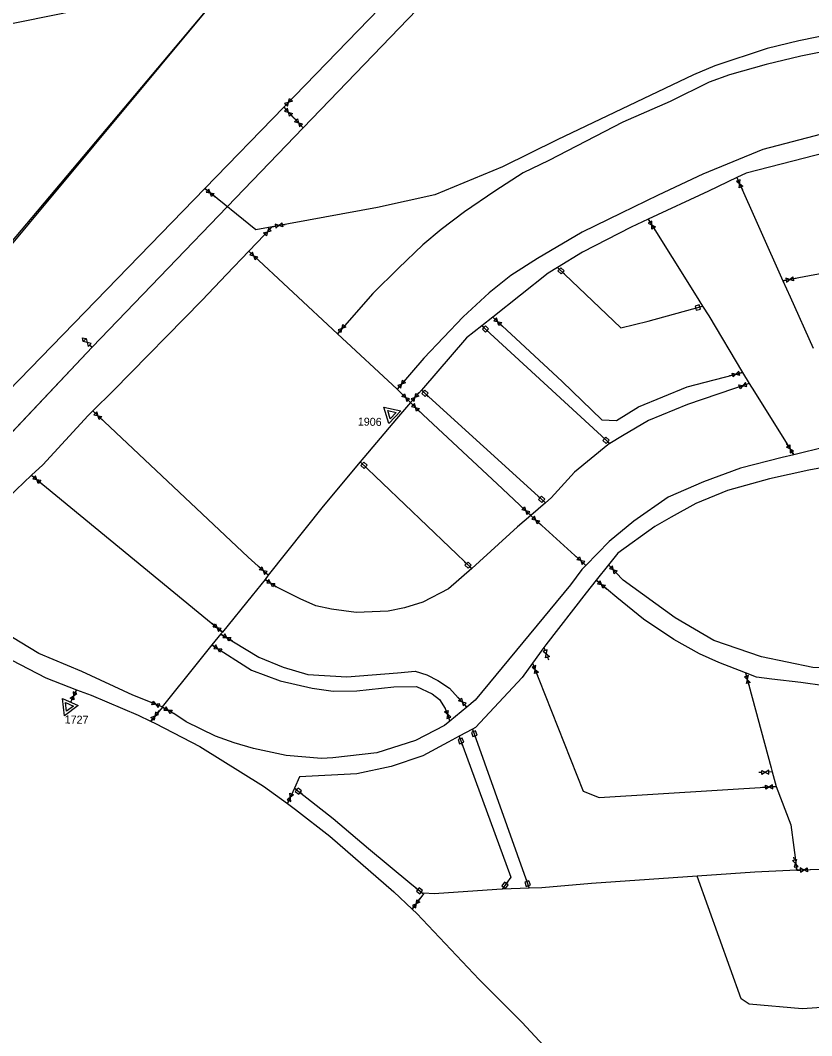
# Model space of a CAD drawing. Extents: x 349903 to 372392, y 368574 to 383062.
# Drawn here: x 363630 to 364124, y 372366 to 373000 of the extents above; entities that cross this region are included whole.
import ezdxf

# ---------------------------------------------------------------- set-up
doc = ezdxf.new("R2010")
doc.units = 0
for name, color, linetype in [('Niveau 1', 7, 'Continuous'), ('Niveau 10', 7, 'Continuous'), ('Niveau 2', 7, 'Continuous'), ('Niveau 3', 7, 'Continuous'), ('Niveau 8', 7, 'Continuous')]:
    doc.layers.add(name, color=color, linetype=linetype)

msp = doc.modelspace()

# ---------------------------------------------------------------- linework, layer by layer
at = {"layer": 'Niveau 1'}
for p, q in [((363794.398, 372946.095), (363795.868, 372947.601)), ((363798.925, 372950.737), (363800.253, 372952.098)), ((363794.398, 372946.095), (363795.842, 372944.564)), ((363798.849, 372941.38), (363800.154, 372939.997)), ((363802.105, 372937.95), (363800.804, 372939.337)), ((363806.543, 372933.223), (363805.103, 372934.757)), ((364077.454, 372902.271), (364078.305, 372900.346)), ((363745.073, 372895.381), (363746.713, 372894.062)), ((363750.126, 372891.317), (363751.607, 372890.126)), ((364080.076, 372896.341), (364080.845, 372894.602)), ((363787.143, 372871.393), (363785.689, 372869.871)), ((363787.143, 372871.393), (363789.212, 372871.781)), ((363793.516, 372872.589), (363795.385, 372872.939)), ((364022.042, 372876.157), (364023.152, 372874.369)), ((363782.665, 372866.704), (363781.351, 372865.329)), ((364025.462, 372870.649), (364026.466, 372869.033)), ((363772.563, 372856.214), (363774.103, 372854.78)), ((363777.309, 372851.797), (363778.701, 372850.501)), ((364106.192, 372837.789), (364108.262, 372838.169)), ((364112.569, 372838.96), (364114.44, 372839.303)), ((363924.923, 372815.068), (363926.464, 372813.635)), ((363832.288, 372809.52), (363833.553, 372810.939)), ((363929.672, 372810.654), (363931.065, 372809.359)), ((363827.973, 372804.68), (363829.374, 372806.25)), ((363869.525, 372774.885), (363870.774, 372776.319)), ((364074.75, 372778.888), (364072.91, 372778.408)), ((364081.024, 372780.525), (364078.988, 372779.994)), ((363865.266, 372769.996), (363866.648, 372771.583)), ((364079.052, 372771.508), (364077.255, 372770.887)), ((364085.18, 372773.628), (364083.191, 372772.94)), ((363869.031, 372766.284), (363867.694, 372767.636)), ((363877.832, 372766.575), (363879.076, 372768.013)), ((363873.589, 372761.673), (363872.11, 372763.17)), ((363873.589, 372761.673), (363874.966, 372763.265)), ((363873.589, 372761.673), (363875.093, 372760.201)), ((363878.223, 372757.138), (363879.582, 372755.809)), ((363675.157, 372756.434), (363676.696, 372754.999)), ((363679.899, 372752.012), (363681.29, 372750.716)), ((364109.487, 372734.589), (364108.481, 372736.202)), ((364112.916, 372729.086), (364111.803, 372730.872)), ((363636.933, 372716.325), (363638.552, 372714.98)), ((363641.921, 372712.183), (363643.384, 372710.968)), ((363943.961, 372695.625), (363942.578, 372696.93)), ((363948.679, 372691.177), (363947.148, 372692.621)), ((363948.679, 372691.177), (363950.236, 372689.761)), ((363953.478, 372686.816), (363954.885, 372685.537)), ((363978.356, 372664.364), (363976.95, 372665.644)), ((363779.943, 372658.177), (363778.54, 372659.46)), ((363983.15, 372659.999), (363981.594, 372661.416)), ((363997.27, 372660.376), (363998.717, 372658.848)), ((364001.73, 372655.669), (364003.037, 372654.289)), ((363782.705, 372651.253), (363784.467, 372650.102)), ((363784.727, 372653.801), (363783.175, 372655.222)), ((363989.588, 372650.835), (363991.201, 372649.483)), ((363788.134, 372647.709), (363789.727, 372646.669)), ((363994.558, 372646.67), (363996.015, 372645.449)), ((363751.072, 372622.466), (363749.6, 372623.668)), ((363756.094, 372618.364), (363754.464, 372619.695)), ((363755.124, 372617.175), (363756.928, 372616.092)), ((363760.684, 372613.84), (363762.315, 372612.862)), ((363751.367, 372609.249), (363749.591, 372610.394)), ((363755.041, 372606.882), (363756.639, 372605.852)), ((363956.92, 372608.822), (363957.642, 372606.845)), ((363949.83, 372598.957), (363950.62, 372597.007)), ((363959.145, 372602.732), (363959.797, 372600.946)), ((363952.265, 372592.948), (363952.98, 372591.186)), ((364082.846, 372592.881), (364083.394, 372590.849)), ((364084.536, 372586.621), (364085.032, 372584.786)), ((363664.038, 372580.482), (363664.953, 372582.387)), ((363662.146, 372576.542), (363661.323, 372574.828)), ((363712.385, 372574.096), (363710.616, 372574.792)), ((363904.494, 372576.333), (363903.228, 372577.751)), ((363716.52, 372569.296), (363715.196, 372567.66)), ((363718.418, 372571.719), (363716.46, 372572.491)), ((363718.418, 372571.719), (363720.233, 372570.653)), ((363724.01, 372568.437), (363725.65, 372567.475)), ((363895.98, 372568.911), (363895.322, 372570.695)), ((363908.81, 372571.494), (363907.409, 372573.065)), ((363712.442, 372564.255), (363711.247, 372562.776)), ((363898.224, 372562.828), (363897.496, 372564.802)), ((364092.993, 372530.698), (364091.095, 372530.58)), ((364099.464, 372531.102), (364097.364, 372530.971)), ((363799.434, 372517.172), (363800.201, 372518.912)), ((364095.38, 372521.522), (364093.482, 372521.409)), ((364101.852, 372521.908), (364099.751, 372521.783)), ((363796.817, 372511.24), (363797.666, 372513.165)), ((364113.402, 372476.006), (364112.948, 372477.852)), ((364114.953, 372469.71), (364114.45, 372471.753)), ((364114.953, 372469.71), (364117.055, 372469.792)), ((364121.432, 372469.965), (364123.332, 372470.039)), ((363874.664, 372445.254), (363875.895, 372446.961)), ((363878.456, 372450.514), (363879.568, 372452.056))]:
    msp.add_line(p, q, dxfattribs=at)
for points in [[(363798.015, 372951.619), (363799.827, 372949.863), (363794.969, 372948.497), (363796.77, 372946.728)], [(363799.768, 372942.253), (363797.939, 372940.515), (363796.774, 372945.425), (363794.933, 372943.699)], [(363801.183, 372937.08), (363803.018, 372938.812), (363804.169, 372933.899), (363806.014, 372935.621)], [(364081.234, 372896.857), (364078.929, 372895.83), (364079.47, 372900.846), (364077.159, 372899.833)], [(363750.917, 372892.308), (363749.342, 372890.337), (363747.518, 372895.042), (363745.931, 372893.08)], [(363793.278, 372873.834), (363793.751, 372871.356), (363788.991, 372873.03), (363789.448, 372870.548)], [(364026.538, 372871.321), (364024.398, 372869.983), (364024.237, 372875.026), (364022.089, 372873.702)], [(363783.584, 372865.831), (363781.754, 372867.568), (363786.597, 372868.985), (363784.778, 372870.734)], [(363778.17, 372852.728), (363776.457, 372850.875), (363774.978, 372855.699), (363773.253, 372853.857)], [(364112.337, 372840.206), (364112.8, 372837.725), (364108.047, 372839.419), (364108.494, 372836.935)], [(363930.533, 372811.585), (363928.821, 372809.732), (363927.338, 372814.555), (363925.614, 372812.712)], [(363831.339, 372810.36), (363833.228, 372808.687), (363828.436, 372807.105), (363830.314, 372805.42)], [(364075.074, 372777.662), (364074.429, 372780.102), (364079.295, 372778.763), (364078.665, 372781.207)], [(363868.566, 372775.715), (363870.474, 372774.064), (363865.701, 372772.426), (363867.599, 372770.763)], [(364079.471, 372770.311), (364078.638, 372772.693), (364083.593, 372771.737), (364082.775, 372774.125)], [(363868.132, 372765.39), (363869.921, 372767.169), (363871.198, 372762.288), (363872.998, 372764.056)], [(363876.871, 372767.402), (363878.783, 372765.757), (363874.016, 372764.105), (363875.919, 372762.447)], [(363879.107, 372758.047), (363877.348, 372756.239), (363875.99, 372761.098), (363874.219, 372759.3)], [(363680.761, 372752.943), (363679.046, 372751.092), (363677.571, 372755.917), (363675.844, 372754.077)], [(364108.412, 372733.915), (364110.55, 372735.256), (364110.719, 372730.213), (364112.865, 372731.541)], [(363642.728, 372713.161), (363641.123, 372711.215), (363639.373, 372715.947), (363637.754, 372714.011)], [(363943.094, 372694.7), (363944.82, 372696.541), (363946.268, 372691.708), (363948.005, 372693.538)], [(363954.328, 372687.757), (363952.636, 372685.885), (363951.099, 372690.69), (363949.396, 372688.829)], [(363977.505, 372663.424), (363979.198, 372665.295), (363980.73, 372660.487), (363982.435, 372662.348)], [(363779.09, 372657.239), (363780.787, 372659.106), (363782.308, 372654.295), (363784.017, 372656.152)], [(364002.647, 372656.544), (364000.821, 372654.803), (363999.647, 372659.711), (363997.81, 372657.981)], [(363788.824, 372648.773), (363787.452, 372646.655), (363785.172, 372651.157), (363783.786, 372649.048)], [(363995.369, 372647.645), (363993.754, 372645.706), (363992.026, 372650.446), (363990.399, 372648.517)], [(363750.273, 372621.481), (363751.863, 372623.44), (363753.651, 372618.722), (363755.254, 372620.671)], [(363761.333, 372614.929), (363760.042, 372612.761), (363757.593, 372617.173), (363756.288, 372615.013)], [(363755.725, 372607.95), (363754.365, 372605.825), (363752.058, 372610.313), (363750.685, 372608.196)], [(363960.335, 372603.171), (363957.967, 372602.297), (363958.838, 372607.268), (363956.465, 372606.409)], [(363953.439, 372593.428), (363951.104, 372592.473), (363951.801, 372597.47), (363949.459, 372596.53)], [(364085.76, 372586.956), (364083.326, 372586.29), (364084.623, 372591.167), (364082.184, 372590.516)], [(363663.291, 372575.997), (363661.013, 372577.082), (363665.179, 372579.929), (363662.908, 372581.028)], [(363711.924, 372572.914), (363712.842, 372575.265), (363715.982, 372571.316), (363716.915, 372573.66)], [(363903.55, 372575.485), (363905.428, 372577.171), (363906.454, 372572.231), (363908.342, 372573.904)], [(363713.431, 372563.46), (363711.464, 372565.041), (363716.173, 372566.851), (363714.217, 372568.445)], [(363724.649, 372569.533), (363723.378, 372567.352), (363720.887, 372571.74), (363719.602, 372569.569)], [(363894.791, 372568.468), (363897.156, 372569.349), (363896.301, 372564.376), (363898.671, 372565.242)], [(364093.076, 372529.433), (364092.911, 372531.951), (364097.429, 372529.705), (364097.28, 372532.224)], [(364095.459, 372520.257), (364095.301, 372522.775), (364099.813, 372520.516), (364099.671, 372523.036)], [(363798.272, 372517.681), (363800.584, 372516.669), (363796.512, 372513.69), (363798.817, 372512.664)], [(364112.172, 372475.699), (364114.62, 372476.31), (364113.215, 372471.463), (364115.667, 372472.059)], [(364121.378, 372471.232), (364121.485, 372468.711), (364117.019, 372471.061), (364117.111, 372468.539)], [(363877.425, 372451.252), (363879.477, 372449.782), (363874.874, 372447.713), (363876.917, 372446.232)]]:
    msp.add_lwpolyline(points, close=True, dxfattribs=at)
at = {"layer": 'Niveau 10'}
for p, q in [((363982.809, 373140.47), (363794.398, 372946.095)), ((363794.398, 372946.095), (363745.073, 372895.381)), ((363794.398, 372946.095), (363806.543, 372933.223)), ((363745.073, 372895.381), (363535.863, 372679.803)), ((363918.11, 372809.653), (363997.984, 372736.039)), ((363880.347, 372769.478), (363957.894, 372699.12)), ((363842.196, 372724.617), (363911.791, 372657.981)), ((363636.933, 372716.325), (363756.094, 372618.364)), ((363664.953, 372582.387), (363661.323, 372574.828)), ((363912.267, 372557.794), (363947.727, 372458.361))]:
    msp.add_line(p, q, dxfattribs=at)
for points in [[(363691.691, 373013.023), (363665.555, 373006.438), (363560.368, 372985.3), (363466.328, 372961.975), (363420.763, 372957.116), (363358.717, 372961.975), (363317.999, 372978.497), (363274.757, 373004.932), (363229.192, 373044.806), (363099.863, 373176.5)], [(363937.464, 373069.402), (363806.543, 372933.223)], [(364311.603, 373023.61), (364290.607, 373019.611), (364247.782, 373011.512), (364218.07, 373006.005), (364178.347, 372999.526), (364139.688, 372992.399), (364116.113, 372987.54), (364096.413, 372982.68), (364063.567, 372971.99), (364050.421, 372966.32), (363965.162, 372925.826), (363930.929, 372908.981), (363888.718, 372891.487), (363852.87, 372883.389), (363787.143, 372871.393)], [(363758.548, 373021.97), (363387.656, 372576.394), (363076.85, 372194.567), (362987.022, 372096.447), (362639.639, 371713.502), (362501.408, 371562.226)], [(363758.548, 373021.97), (363587.181, 372818.111), (363052.431, 372166.564), (362880.62, 371984.026)], [(364312.283, 373014.384), (364290.156, 373009.868), (364244.05, 373002.044), (364206.658, 372995.129), (364187.235, 372991.307), (364148.317, 372984.228), (364117.278, 372978.038), (364095.677, 372972.757), (364072.896, 372966.276), (364060.19, 372961.724), (364035.685, 372949.707), (364006.17, 372936.779), (363959.937, 372912.856), (363943.963, 372905.208), (363926.174, 372893.737), (363907.297, 372880.81), (363892.666, 372869.777), (363881.23, 372860.126), (363866.164, 372845.56), (363850.009, 372829.719), (363827.973, 372804.68)], [(364312.283, 372962.676), (364295.071, 372959.015), (364204.161, 372944.235), (364143.875, 372932.915), (364093.718, 372919.708), (364056.1, 372904.3), (364028.2, 372891.093), (364005.157, 372879.96), (363980.706, 372868.011), (363952.806, 372851.66), (363936.191, 372840.969), (363922.712, 372830.277), (363906.411, 372815.184), (363881.959, 372789.399), (363865.266, 372769.996)], [(363806.543, 372933.223), (363674.699, 372796.232)], [(364179.022, 372927.19), (364155.224, 372923.498), (364083.14, 372905.028), (364077.454, 372902.271)], [(364179.022, 372927.19), (364180.573, 372851.562), (364106.192, 372837.789)], [(364077.454, 372902.271), (364059.634, 372893.632), (364022.042, 372876.157)], [(364077.454, 372902.271), (364106.192, 372837.789)], [(363787.143, 372871.393), (363777.072, 372869.555), (363745.073, 372895.381)], [(363772.563, 372856.214), (363787.143, 372871.393)], [(364022.042, 372876.157), (364011.447, 372871.232), (363981.043, 372855.513), (363965.336, 372846.06)], [(364022.042, 372876.157), (364051.927, 372828.37), (364055.962, 372821.898)], [(363675.157, 372756.434), (363687.793, 372769.1), (363743.471, 372825.701), (363758.656, 372841.735), (363772.563, 372856.214)], [(363772.563, 372856.214), (363827.973, 372804.68)], [(363965.336, 372846.06), (363959.496, 372842.545), (363924.923, 372815.068)], [(363965.336, 372846.06), (364004.938, 372808.25), (364022.039, 372812.472), (364055.962, 372821.898)], [(364106.192, 372837.789), (364110.652, 372827.783), (364124.962, 372795.753)], [(364055.962, 372821.898), (364059.798, 372815.744), (364081.024, 372780.525)], [(363924.923, 372815.068), (363918.11, 372809.653)], [(363924.923, 372815.068), (363968.194, 372774.834), (363993.118, 372751.002), (364002.321, 372750.425), (364015.933, 372759.074), (364046.418, 372771.567), (364081.024, 372780.525)], [(363918.11, 372809.653), (363908.567, 372802.069), (363880.347, 372769.478)], [(363827.973, 372804.68), (363865.266, 372769.996)], [(363674.699, 372796.232), (363008.494, 372089.814), (362807.398, 371853.198), (362660.336, 371693.513)], [(363674.699, 372796.232), (363184.694, 372275.841)], [(364081.024, 372780.525), (364085.18, 372773.628)], [(363865.266, 372769.996), (363865.534, 372769.747), (363873.589, 372761.673)], [(364085.18, 372773.628), (364046.574, 372760.446), (364022.178, 372750.526), (364006.025, 372740.936), (363997.984, 372736.039)], [(364085.18, 372773.628), (364088.333, 372768.397), (364112.916, 372729.086)], [(363880.347, 372769.478), (363873.589, 372761.673)], [(363873.589, 372761.673), (363864.805, 372751.529), (363842.196, 372724.617)], [(363873.589, 372761.673), (363878.409, 372756.841), (363927.69, 372711.035), (363948.679, 372691.177)], [(363636.933, 372716.325), (363643.836, 372722.899), (363672.341, 372753.611), (363675.157, 372756.434)], [(363675.157, 372756.434), (363772.242, 372665.236), (363784.727, 372653.801)], [(363997.984, 372736.039), (363996.794, 372735.314), (363976.024, 372718.118), (363961.519, 372702.245), (363957.894, 372699.12)], [(364306.005, 372730.468), (364295.758, 372730.468), (364254.548, 372731.652), (364226.446, 372732.126), (364191.968, 372729.757), (364156.142, 372725.73), (364122.372, 372719.571), (364097.859, 372714.123), (364071.48, 372706.779), (364051.713, 372698.606), (364036.363, 372690.078), (364026.209, 372684.393), (364003.066, 372667.574), (363997.27, 372660.376)], [(364151.446, 372736.884), (364133.181, 372734.095), (364112.916, 372729.086)], [(364112.916, 372729.086), (364105.714, 372727.306), (364079.651, 372720.77), (364056.595, 372712.223), (364034.541, 372702.671), (364012.989, 372687.588), (363997.651, 372674.899), (363983.15, 372659.999)], [(364306.005, 372730.468), (364296.34, 372691.555), (364284.785, 372666.521), (364269.503, 372645.97), (364253.849, 372630.276), (364234.094, 372617.198), (364213.966, 372607.857), (364187.875, 372599.637), (364165.139, 372596.274), (364135.693, 372595.9), (364124.884, 372596.274), (364092.829, 372603), (364063.011, 372613.088), (364038.783, 372627.287), (364006.355, 372650.827), (363997.27, 372660.376)], [(364318.306, 372730.468), (364308.152, 372691.825), (364303.01, 372679.1), (364297.064, 372667.341), (364291.28, 372656.71), (364286.812, 372648.383), (364278.938, 372638.551), (364269.136, 372629.364), (364257.085, 372619.21), (364248.087, 372612.682), (364224.466, 372599.143), (364192.568, 372589.955), (364173.446, 372586.087), (364155.128, 372584.475), (364140.744, 372584.314), (364132.228, 372584.798), (364117.285, 372586.893), (364099.288, 372588.988), (364089.647, 372590.278), (364082.846, 372592.881)], [(363842.196, 372724.617), (363819.045, 372697.06), (363784.727, 372653.801)], [(363573.29, 372650.886), (363622.523, 372702.602), (363636.933, 372716.325)], [(363957.894, 372699.12), (363948.679, 372691.177)], [(363948.679, 372691.177), (363940.42, 372684.057), (363911.791, 372657.981)], [(363948.679, 372691.177), (363983.15, 372659.999)], [(363527.43, 372670.868), (363619.026, 372603.654), (363645.797, 372589.72), (363664.953, 372582.387)], [(363911.791, 372657.981), (363897.278, 372645.295), (363881.327, 372637.084), (363869.831, 372633.483), (363859.635, 372631.438), (363839.661, 372630.574), (363824.279, 372632.619), (363814.507, 372634.779), (363804.592, 372639.101), (363789.727, 372646.669), (363782.705, 372651.253)], [(363983.15, 372659.999), (363980.645, 372657.425), (363973.418, 372647.836), (363914.006, 372575.746), (363908.81, 372571.494)], [(363997.27, 372660.376), (363989.588, 372650.835)], [(363718.418, 372571.719), (363700.107, 372578.87), (363668.335, 372593.743), (363641.505, 372605.075), (363619.264, 372618.531), (363573.29, 372650.886)], [(363782.705, 372651.253), (363774.776, 372641.258), (363756.094, 372618.364)], [(363784.727, 372653.801), (363782.705, 372651.253)], [(363989.588, 372650.835), (363983.229, 372642.938), (363958.03, 372610.366), (363956.92, 372608.822)], [(364082.846, 372592.881), (364066.073, 372599.304), (364054.022, 372604.784), (364038.114, 372613.81), (364019.039, 372626.382), (364002.489, 372639.921), (363989.588, 372650.835)], [(363756.094, 372618.364), (363755.124, 372617.175)], [(363755.124, 372617.175), (363749.591, 372610.394)], [(363755.121, 372617.05), (363778.87, 372602.608), (363793.987, 372596.47), (363809.486, 372591.866), (363833.788, 372590.331), (363865.361, 372593.017), (363876.459, 372593.976), (363883.731, 372591.674), (363890.619, 372588.221), (363897.891, 372583.426), (363908.807, 372571.369)], [(363749.591, 372610.394), (363740.301, 372599.009), (363718.418, 372571.719)], [(363749.591, 372610.394), (363774.281, 372594.484), (363792.268, 372587.962), (363812.168, 372583.359), (363825.371, 372581.44), (363840.106, 372581.632), (363863.259, 372584.126), (363877.419, 372584.318), (363887.178, 372579.714), (363891.77, 372576.261), (363895.322, 372570.695), (363898.224, 372562.828)], [(363956.92, 372608.822), (363949.83, 372598.957)], [(363949.83, 372598.957), (363943.389, 372589.994), (363914.153, 372558.819), (363912.267, 372557.794)], [(363949.83, 372598.957), (363981.357, 372518.948), (363991.401, 372515.136), (364101.852, 372521.908)], [(364082.846, 372592.881), (364098.814, 372533.604), (364099.464, 372531.102)], [(363664.953, 372582.387), (363674.113, 372578.881), (363703.458, 372566.495), (363711.247, 372562.776)], [(363718.412, 372571.344), (363711.241, 372562.401)], [(363898.224, 372562.828), (363894.766, 372559.997), (363876.656, 372550.718), (363852.474, 372542.928), (363825.114, 372539.741), (363818.053, 372539.387), (363795.901, 372541.334), (363775.426, 372545.584), (363763.423, 372549.302), (363751.773, 372553.374), (363733.468, 372562.404), (363725.65, 372567.475), (363718.418, 372571.719)], [(363908.81, 372571.494), (363898.224, 372562.828)], [(363711.247, 372562.776), (363714.269, 372561.334), (363742.07, 372546.883), (363781.711, 372522.111), (363796.817, 372511.24)], [(363912.267, 372557.794), (363904.003, 372553.304)], [(363904.003, 372553.304), (363897.15, 372549.58), (363881.327, 372541.053), (363861.537, 372534.42), (363840.047, 372529.919), (363804.222, 372528.024), (363801.09, 372520.933)], [(363904.003, 372553.304), (363936.324, 372465.307), (363930.723, 372457.745)], [(364099.464, 372531.102), (364101.852, 372521.908)], [(363801.09, 372520.933), (363796.817, 372511.24)], [(363801.09, 372520.933), (363825.237, 372501.865), (363847.411, 372483.293), (363873.086, 372461.795), (363881.617, 372454.838)], [(364101.852, 372521.908), (364111.038, 372498.041), (364114.953, 372469.71)], [(363796.817, 372511.24), (363801.789, 372507.66), (363823.119, 372490.89), (363863.075, 372456.089), (363874.664, 372445.254)], [(364266.291, 372479.858), (364239.291, 372475.121), (364205.658, 372473.226), (364171.552, 372471.332), (364123.277, 372469.947), (364114.896, 372469.716)], [(364114.953, 372469.71), (364088.547, 372468.528), (363986.588, 372461.374), (363955.66, 372458.648), (363947.727, 372458.361)], [(364195.094, 372388.268), (364118.166, 372383.15), (364085.159, 372385.997), (364080.163, 372389.409), (364052.55, 372465.988)], [(363881.617, 372454.838), (363874.664, 372445.254)], [(363930.723, 372457.745), (363927.452, 372457.626), (363888.367, 372454.9), (363881.91, 372455.241), (363881.617, 372454.838)], [(363947.727, 372458.361), (363930.723, 372457.745)], [(363874.664, 372445.254), (363877.469, 372442.632), (363916.443, 372401.463), (363943.214, 372374.61), (363964.837, 372351.371), (363982.057, 372333.98)]]:
    msp.add_lwpolyline(points, dxfattribs=at)
at = {"layer": 'Niveau 2'}
for points in [[(363867.476, 372756.454), (363860.125, 372748.599), (363856.998, 372758.893)], [(363864.632, 372755.555), (363860.958, 372751.628), (363859.396, 372756.777)], [(363666.062, 372572.594), (363657.459, 372566.134), (363656.166, 372576.814)], [(363663.105, 372572.201), (363658.804, 372568.973), (363658.161, 372574.314)]]:
    msp.add_lwpolyline(points, close=True, dxfattribs=at)
at = {"layer": 'Niveau 3'}
for p, q in [((363966.597, 372844.858), (363965.336, 372846.06)), ((363969.781, 372841.819), (363968.606, 372842.939)), ((364050.046, 372820.241), (364051.61, 372820.679)), ((364054.285, 372821.428), (364055.962, 372821.898)), ((363919.389, 372808.47), (363918.11, 372809.653)), ((363922.621, 372805.482), (363921.428, 372806.584)), ((363881.638, 372768.308), (363880.347, 372769.478)), ((363884.898, 372765.35), (363883.695, 372766.441)), ((363993.482, 372740.22), (363994.673, 372739.115)), ((363996.707, 372737.224), (363997.984, 372736.039)), ((363843.458, 372723.416), (363842.196, 372724.617)), ((363846.647, 372720.382), (363845.47, 372721.501)), ((363953.34, 372703.244), (363954.544, 372702.154)), ((363956.602, 372700.289), (363957.894, 372699.12)), ((363907.401, 372662.28), (363908.562, 372661.143)), ((363910.546, 372659.2), (363911.791, 372657.981)), ((363912.874, 372556.161), (363912.267, 372557.794)), ((363904.594, 372551.665), (363904.003, 372553.304)), ((363906.086, 372547.524), (363905.535, 372549.052)), ((363914.405, 372552.034), (363913.839, 372553.557)), ((363802.462, 372519.859), (363801.09, 372520.933)), ((363805.927, 372517.145), (363804.648, 372518.146)), ((363931.771, 372459.137), (363930.723, 372457.745)), ((363934.419, 372462.653), (363933.442, 372461.355)), ((363945.736, 372464.173), (363946.263, 372462.637)), ((363947.162, 372460.009), (363947.727, 372458.361)), ((363876.858, 372458.724), (363878.116, 372457.697)), ((363880.267, 372455.94), (363881.617, 372454.838))]:
    msp.add_line(p, q, dxfattribs=at)
for points in [[(363967.568, 372845.875), (363965.672, 372843.89), (363967.665, 372841.988), (363969.56, 372843.975)], [(364054.664, 372820.073), (364053.924, 372822.718), (364051.271, 372821.975), (364052.012, 372819.33)], [(363920.344, 372809.504), (363918.48, 372807.488), (363920.502, 372805.618), (363922.367, 372807.634)], [(363882.583, 372769.35), (363880.738, 372767.316), (363882.778, 372765.466), (363884.623, 372767.5)], [(363995.75, 372736.193), (363997.619, 372738.205), (363995.601, 372740.08), (363993.732, 372738.068)], [(363844.428, 372724.436), (363842.535, 372722.447), (363844.53, 372720.548), (363846.423, 372722.537)], [(363955.658, 372699.246), (363957.502, 372701.281), (363955.46, 372703.131), (363953.617, 372701.095)], [(363909.562, 372658.194), (363911.483, 372660.156), (363909.516, 372662.083), (363907.594, 372660.121)], [(363914.193, 372556.651), (363911.618, 372555.695), (363912.576, 372553.113), (363915.151, 372554.069)], [(363905.918, 372552.142), (363903.334, 372551.212), (363904.267, 372548.62), (363906.851, 372549.551)], [(363803.329, 372520.967), (363801.636, 372518.805), (363803.804, 372517.107), (363805.498, 372519.269)], [(363930.647, 372459.983), (363932.84, 372458.331), (363934.497, 372460.531), (363932.304, 372462.183)], [(363945.831, 372459.553), (363948.429, 372460.442), (363947.537, 372463.048), (363944.938, 372462.158)], [(363879.378, 372454.849), (363881.115, 372456.977), (363878.981, 372458.719), (363877.244, 372456.591)]]:
    msp.add_lwpolyline(points, close=True, dxfattribs=at)
at = {"layer": 'Niveau 8'}
msp.add_line((363673.185, 372797.693), (363674.699, 372796.232), dxfattribs=at)
for points in [[(363669.155, 372799.818), (363668.664, 372802.053), (363670.901, 372801.64)], [(363669.155, 372799.818), (363670.901, 372801.64), (363672.294, 372796.79), (363674.052, 372798.601)]]:
    msp.add_lwpolyline(points, close=True, dxfattribs=at)

# ---------------------------------------------------------------- texts
at = {"layer": 'Niveau 2'}
for s, p in [('1906', (363840.624, 372747.332)), ('1727', (363657.524, 372561.315))]:
    msp.add_text(s, height=5, rotation=359, dxfattribs=at).set_placement(p)

doc.saveas('drawing.dxf')
